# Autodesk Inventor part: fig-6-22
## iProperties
Created: 2005-04
Part Number: fig-6-22
Document SubType Name: Modeling
Designer: CADCIM
Density: 1 g/cm^3
Author: CADCIM
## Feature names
1. Extrusion1
2. Extrusion2
3. Extrusion3
